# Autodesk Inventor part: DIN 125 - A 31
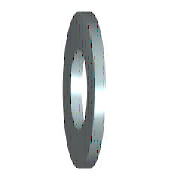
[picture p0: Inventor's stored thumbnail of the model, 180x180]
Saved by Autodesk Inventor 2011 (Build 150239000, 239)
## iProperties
IsCustomPart: 0
Created: 2009-02
Part Number: DIN 125 - A 31
Material: Steel, Mild
Description: Washer
Document SubType Name: Modeling
Standard: DIN 125
Designer: "initialen"
Standards Organization: DIN
Language: en-US
Size Designation: A 31
Categories: <MemberInstance><Categories><Category DisplayName="Fasteners" InternalName="e4da775c-781d-43d5-af7c-5136215cf5a6" Mnemonic="FSTN"><Category DisplayName="Washers
Density: 7.86 g/cm^3
Mass: 53.7071 g
Surface Area: 45.0976 cm^2
Volume: 6.83296 cm^3
Author: "initialen"
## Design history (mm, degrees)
body "Solid1"
sketch "Sketch"
  geometry: C1 r 28 at (0, 0); C2 r 15.5 at (0, 0); 1 further point
  constraints: 2 centre point, 2 coincident
  dimensions: "d0" = 31 diameter of C2 (= SD1); "d1" = 56 diameter of C1 (= SD2)
extrude "Body" new body sketch "Sketch" distance "d2" = 4 (= SD); taper "d3" = 0 deg
workaxis "Work Axis1"
workplane "Work Plane1"
other parameters: "SD1" = 31 [user parameter; used in 1 equation term], "SD2" = 56 [user parameter; used in 1 equation term], "SD" = 4 [user parameter; used in 1 equation term], "d4" = 0, "d5" = 0, "d6" = 0, "d7" = 0
